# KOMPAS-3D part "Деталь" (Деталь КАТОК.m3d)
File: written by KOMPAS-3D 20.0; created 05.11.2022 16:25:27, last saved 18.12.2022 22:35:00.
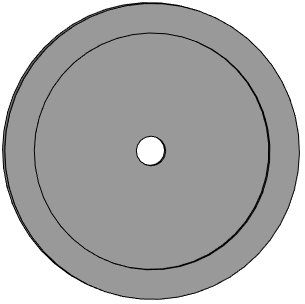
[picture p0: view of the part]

Document properties: Полное имя файла: C:\Users\Семья\Desktop\ДЕТАЛИ ДЛЯ СБОРЩИКА БОРЩЕВИКА\Деталь КАТОК.m3d

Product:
- Part/product: Деталь
    Масса: 0.0166592
- Part/product: Деталь  | designation 01
    Масса: 0.0166592

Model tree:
1. Эскиз:1
2. Элемент выдавливания:2
     Расстояние 1 = 10
3. Элемент выдавливания:3
     Расстояние 1 = 10
4. Элемент выдавливания:4
     Расстояние 1 = 10
5. Эскиз:2  (with: Элемент выдавливания:2)
6. Эскиз:3  (with: Элемент выдавливания:2)
7. Эскиз:5  (with: Элемент выдавливания:2)
8. Элемент выдавливания:7
     Расстояние 2 = 10
9. Элемент выдавливания:8
     Расстояние 2 = 7
10. Элемент выдавливания:10  (with: Элемент выдавливания:8)
     Расстояние 1 = 2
